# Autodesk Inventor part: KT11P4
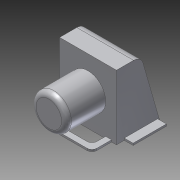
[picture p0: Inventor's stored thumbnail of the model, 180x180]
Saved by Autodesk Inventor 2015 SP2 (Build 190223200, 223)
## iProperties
Created: 2015-08
Part Number: KT11P4
Material: PC/ABS-Kunststoff
Document SubType Name: Modeling
Designer: rYan
Mass: 0.062067 g
Surface Area: 2.29622 cm^2
Volume: 0.173725 cm^3
Density: 0.357273 g/cm^3
Appearance: Glatt - weiß
Author: rYan
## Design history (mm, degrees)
sketch "Skizze2"
  geometry: L1 (0, 0)-(4.4, 0); L2 (2.5, 6.6)-(0, 6.6); L3 (0, 6.6)-(0, 0); L4 (2.5, 6.6)-(4.4, 0); L5 (-0.88, 0)-(5.28, 0) reference; L6 (0, 7.92)-(0, -1.32) reference
  constraints: 8 end point, 1 collinear, 1 horizontal, 1 parallel
  dimensions: "d2" = 6.6 distance of L2.end L1.start; "d3" = 2.5 distance of L2.start L2.end; "d4" = 4.4 distance of L1.start L1.end
extrude "Extrusion1" new body sketch "Skizze2" stored distance "d5" = 5.8; taper "d6" = 0 deg
sketch "Skizze3"
  geometry: L1 (5.8, 0)-(0, 0) reference; L2 (5.8, 6.6)-(5.8, 0) reference; L3 (0, 6.6)-(5.8, 6.6) reference; L4 (0, 0)-(0, 6.6) reference; L5 (0, 6.6)-(0, 0) reference; L6 (0, 3.3)-(5.8, 3.3); L7 (5.8, 0)-(5.8, 6.6) reference; L8 (0, 6.6)-(5.8, 6.6) reference; L9 (2.9, 6.6)-(2.9, 0); C1 r 1.8 at (2.9, 3.3)
  constraints: 4 end point, 4 midpoint, 1 centre point, 1 vertical
  dimensions: "d7" = 3.6 diameter of C1
extrude "Extrusion2" join sketch "Skizze3" distance "d8" = 4; taper "d9" = 0 deg
sketch "Skizze4"
  geometry: L1 (5.8, 0)-(0, 0) reference; L2 (0, -4.4)-(0, 0) reference; L3 (0, -4.4)-(5.8, -4.4) reference; L4 (5.8, 0)-(5.8, -4.4) reference; L5 (0, -4.4)-(0, 0) reference; L6 (0, -3.6)-(-0.9, -3.6); L7 (-0.9, -3.6)-(-0.9, -0.2); L8 (-0.9, -0.2)-(0, -0.2); L9 (0, -0.2)-(0, -3.6); L10 (5.8, -4.4)-(0, -4.4) reference; L11 (5.3, -4.4)-(5.3, -6.4); L12 (5.3, -6.4)-(0.5, -6.4); L13 (0.5, -6.4)-(0.5, -4.4); L14 (2.9, -4.4)-(2.9, 0); L15 (5.8, 0)-(0, 0) reference; L16 (4.7, -4.4)-(4.7, -5.8); L17 (4.7, -5.8)-(1.1, -5.8); L18 (1.1, -5.8)-(1.1, -4.4); L19 (0.5, -4.4)-(1.1, -4.4); L20 (4.7, -4.4)-(5.3, -4.4); L21 (0, -4.4)-(5.8, -4.4) reference; L22 (5.8, -1.9)-(5.8, 0) reference; L23 (5.8, -0.2)-(6.7, -0.2); L24 (6.7, -0.2)-(6.7, -3.6); L25 (6.7, -3.6)-(5.8, -3.6); L26 (5.8, -3.6)-(5.8, -0.2)
  constraints: 34 end point, 9 parallel, 4 horizontal, 4 perpendicular, 3 point on line, 1 collinear, 1 midpoint, 4 other
  dimensions: "d10" = 0.8 distance between parallel lines of L6 L3; "d11" = 3.4 distance of L6.end L7.end; "d12" = 0.9 distance of L7.end L8.end; "d13" = 2 distance of L12.end L13.end; "d14" = 4.8 distance of L11.end L12.end; "d16" = 0.6 distance between parallel lines of L12 L17; "d17" = 0.6 distance between parallel lines of L13 L18 (= d16); "d18" = 0.9 distance of L23.start L23.end (= d12)
extrude "Extrusion3" join sketch "Skizze4" distance "d19" = 0.2; taper "d20" = 0 deg
fillet "Rundung1" dims "d21" = 1
fillet "Rundung2" dims "d22" = 0.5
fillet "Rundung3" dims "d23" = 0.5
node "Volumenkörper1"
node "Projizierte Kontur1"
node "Projizierte Kontur2"
